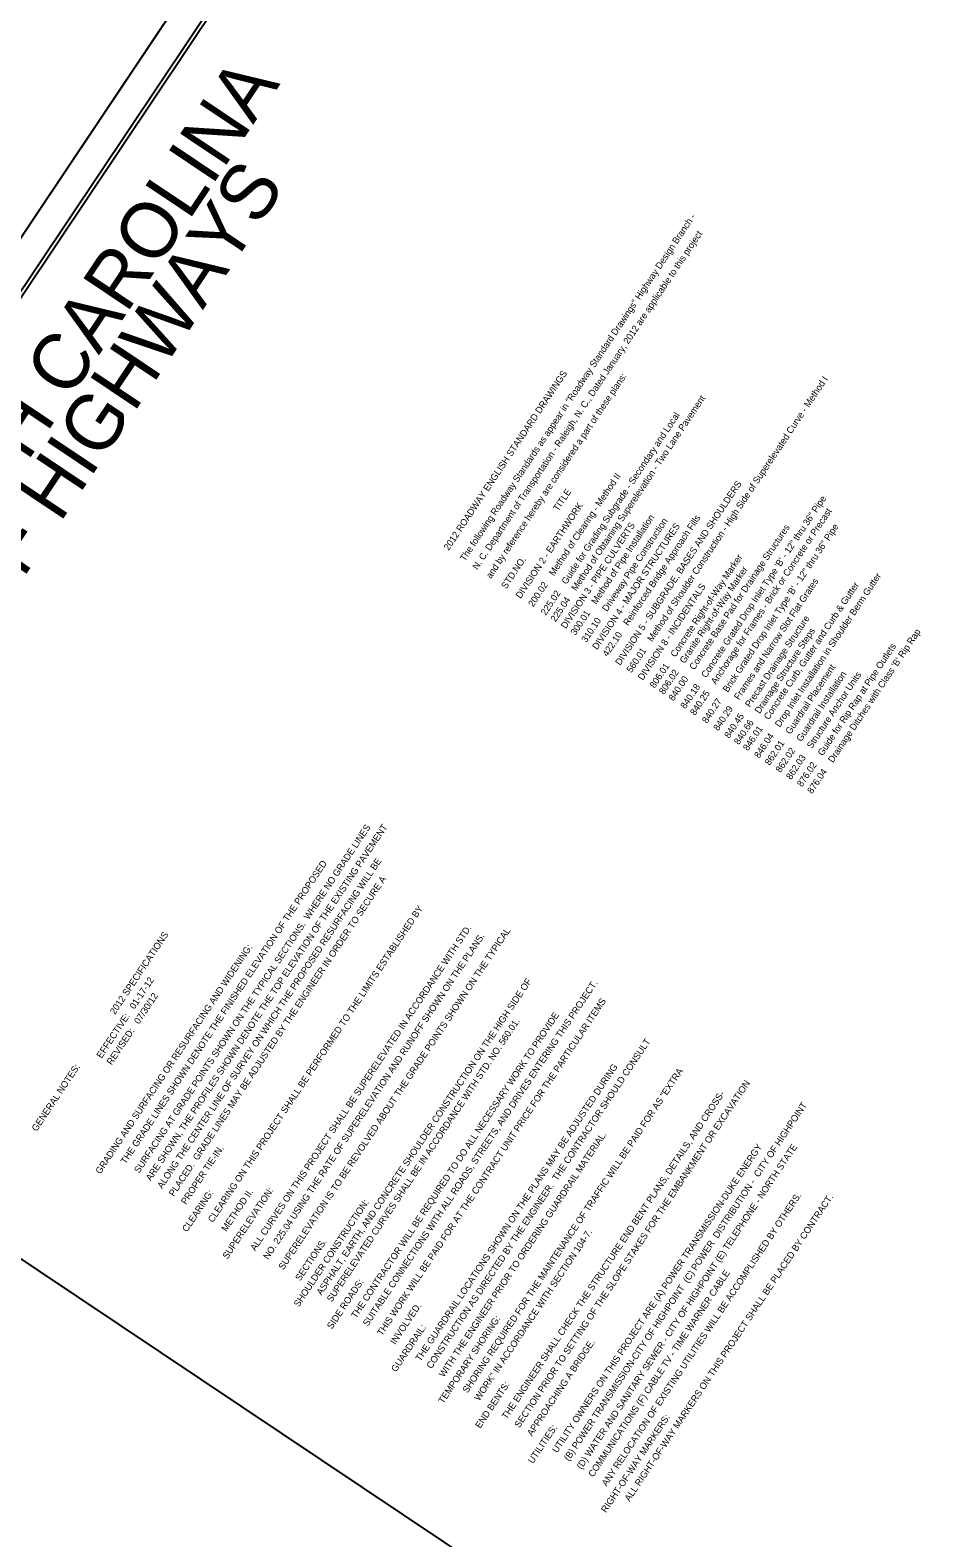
# Model space of a CAD drawing. Extents: x 1715610 to 1720914, y 798298 to 802505.
# Drawn here: x 1719710 to 1720322, y 798983 to 799997 of the extents above; entities that cross this region are included whole.
import ezdxf

# ---------------------------------------------------------------- set-up
doc = ezdxf.new("R2010")
doc.units = 0
for name, color, linetype in [('Default', 7, 'Continuous'), ('Sheet Cutting Line CELL', 7, 'Continuous'), ('Sheet Plan CELL', 7, 'Continuous'), ('Sheet Plot Border Inside CELL', 7, 'Continuous'), ('Sheet Plot Border Outside CELL', 7, 'Continuous'), ('Sheet Title CELL', 7, 'Continuous')]:
    doc.layers.add(name, color=color, linetype=linetype)

msp = doc.modelspace()

# ---------------------------------------------------------------- linework, layer by layer
at = {"layer": 'Default'}
msp.add_lwpolyline([(1719835.5, 798633.5), (1720043.1, 798943.6), (1719661.6, 799198.9), (1719454, 798888.8)], close=True, dxfattribs=at)
at = {"layer": 'Sheet Cutting Line CELL'}
msp.add_line((1720004.3, 800305.9), (1719067.9, 798906.9), dxfattribs=at)
at = {"layer": 'Sheet Plan CELL'}
msp.add_lwpolyline([(1720013.5, 800279.3), (1719179.2, 799032.7), (1720051.8, 798448.7), (1720886.1, 799695.2)], close=True, dxfattribs=at)
at = {"layer": 'Sheet Plot Border Inside CELL'}
msp.add_lwpolyline([(1719968.5, 798319.7), (1720895.2, 799704.2), (1720018.4, 800291.1), (1719091.7, 798906.6)], close=True, dxfattribs=at)
at = {"layer": 'Sheet Plot Border Outside CELL'}
msp.add_lwpolyline([(1719977.9, 798297.8), (1720914.3, 799696.9), (1720004.3, 800305.9), (1719067.9, 798906.9)], close=True, dxfattribs=at)

# ---------------------------------------------------------------- texts
at = {"layer": 'Default'}
for s, p in [('The following Roadway Standards as appear in "Roadway Standard Drawings" Highway Design Branch -', (1720003, 799639.3)), ('N. C. Department of Transportation - Raleigh, N. C., Dated January, 2012 are applicable to this project', (1720011.4, 799633.6)), ('2012 ROADWAY ENGLISH STANDARD DRAWINGS', (1719992.1, 799646.6)), ('and by reference hereby are considered a part of these plans:', (1720020.5, 799627.6)), ('560.01    Method of Shoulder Construction - High Side of Superelevated Curve - Method I', (1720115.1, 799564.3)), ('225.04    Method of Obtaining Superelevation - Two Lane Pavement', (1720064, 799598.5)), ('225.02    Guide for Grading Subgrade - Secondary and Local', (1720057.4, 799602.9)), ('200.02    Method of Clearing - Method II', (1720048.9, 799608.6)), ('STD.NO.                       TITLE', (1720030.8, 799620.7)), ('DIVISION 5 - SUBGRADE, BASES AND SHOULDERS', (1720107.5, 799569.3)), ('DIVISION 2 - EARTHWORK', (1720040.5, 799614.2)), ('840.18    Concrete Grated Drop Inlet Type \'B\' - 12" thru 36" Pipe', (1720151.4, 799540)), ('300.01    Method of Pipe Installation ', (1720077.4, 799589.5)), ('310.10    Driveway Pipe Construction', (1720084.7, 799584.6)), ('422.10    Reinforced Bridge Approach Fills', (1720098.9, 799575.1)), ('840.25    Anchorage for Frames - Brick or Concrete or Precast', (1720157.9, 799535.6)), ('DIVISION 3 - PIPE CULVERTS', (1720070.9, 799593.9)), ('DIVISION 4 - MAJOR STRUCTURES', (1720092, 799579.8)), ('840.00    Concrete Base Pad for Drainage Structures', (1720143.4, 799545.3)), ('840.27    Brick Grated Drop Inlet Type \'B\' - 12" thru 36" Pipe', (1720165.9, 799530.3)), ('806.01    Concrete Right-of-Way Marker', (1720130.7, 799553.9)), ('806.02    Granite Right-of-Way Marker', (1720136.9, 799549.7)), ('840.29    Frames and Narrow Slot Flat Grates', (1720173.5, 799525.2)), ('846.04    Drop Inlet Installation in Shoulder Berm Gutter', (1720201, 799506.8)), ('DIVISION 8 - INCIDENTALS', (1720122.7, 799559.2)), ('846.01    Concrete Curb, Gutter and Curb & Gutter', (1720193.5, 799511.8)), ('840.45    Precast Drainage Structure', (1720180.9, 799520.2)), ('840.66    Drainage Structure Steps', (1720187.4, 799515.9)), ("876.04    Drainage Ditches with Class 'B' Rip Rap", (1720236.7, 799482.9)), ('876.02    Guide for Rip Rap at Pipe Outlets', (1720229.8, 799487.5)), ('862.01    Guardrail Placement', (1720208.1, 799502)), ('862.02    Guardrail Installation', (1720215.4, 799497.1)), ('862.03    Structure Anchor Units', (1720222.5, 799492.4)), ('         SURFACING AT GRADE POINTS SHOWN ON THE TYPICAL SECTIONS.  WHERE NO GRADE LINES ', (1719775.4, 799215.1)), ('         ARE SHOWN, THE PROFILES SHOWN DENOTE THE TOP ELEVATION OF THE EXISTING PAVEMENT ', (1719783.2, 799209.9)), ('         THE GRADE LINES SHOWN DENOTE THE FINISHED ELEVATION OF THE PROPOSED ', (1719766.3, 799221.2)), ('         ALONG THE CENTER LINE OF SURVEY ON WHICH THE PROPOSED RESURFACING WILL BE ', (1719790.9, 799204.7)), ('         PLACED.  GRADE LINES MAY BE ADJUSTED BY THE ENGINEER IN ORDER TO SECURE A ', (1719798.7, 799199.5)), ('         CLEARING ON THIS PROJECT SHALL BE PERFORMED TO THE LIMITS ESTABLISHED BY ', (1719825, 799181.9)), ('         ALL CURVES ON THIS PROJECT SHALL BE SUPERELEVATED IN ACCORDANCE WITH STD. ', (1719853.5, 799162.8)), ('GENERAL NOTES:                         2012 SPECIFICATIONS', (1719714.8, 799255.7)), ('         NO. 225.04 USING THE RATE OF SUPERELEVATION AND RUNOFF SHOWN ON THE PLANS.', (1719862.2, 799157)), ('         SUPERELEVATION IS TO BE REVOLVED ABOUT THE GRADE POINTS SHOWN ON THE TYPICAL ', (1719872.5, 799150.1)), ('GRADING AND SURFACING OR RESURFACING AND WIDENING:  ', (1719757.7, 799227)), ('                                       EFFECTIVE:   01-17-12', (1719722.2, 799250.7)), ('         ASPHALT, EARTH, AND CONCRETE SHOULDER CONSTRUCTION ON THE HIGH SIDE OF', (1719898.1, 799133)), ('         SUITABLE CONNECTIONS WITH ALL ROADS, STREETS, AND DRIVES ENTERING THIS PROJECT.  ', (1719929.3, 799112.1)), ('                                       REVISED:   07/30/12', (1719729, 799246.2)), ('         THIS WORK WILL BE PAID FOR AT THE CONTRACT UNIT PRICE FOR THE PARTICULAR ITEMS ', (1719938.9, 799105.7)), ('         THE CONTRACTOR WILL BE REQUIRED TO DO ALL NECESSARY WORK TO PROVIDE ', (1719921.4, 799117.4)), ('         SUPERELEVATED CURVES SHALL BE IN ACCORDANCE WITH STD. NO. 560.01.', (1719905, 799128.4)), ('         CONSTRUCTION AS DIRECTED BY THE ENGINEER.  THE CONTRACTOR SHOULD CONSULT', (1719972.1, 799083.5)), ('         THE GUARDRAIL LOCATIONS SHOWN ON THE PLANS MAY BE ADJUSTED DURING ', (1719964.7, 799088.5)), ('         SHORING REQUIRED FOR THE MAINTENANCE OF TRAFFIC WILL BE PAID FOR AS "EXTRA ', (1719996.4, 799067.2)), ('         THE ENGINEER SHALL CHECK THE STRUCTURE END BENT PLANS, DETAILS, AND CROSS-', (1720022.8, 799049.5)), ('         SECTION PRIOR TO SETTING OF THE SLOPE STAKES FOR THE EMBANKMENT OR EXCAVATION ', (1720031.3, 799043.8)), ('         (B) POWER TRANSMISSION-CITY OF HIGHPOINT  (C) POWER  DISTRIBUTION -  CITY OF HIGHPOINT', (1720064.6, 799021.5)), ('         WITH THE ENGINEER PRIOR TO ORDERING GUARDRAIL MATERIAL.', (1719980.5, 799077.8)), ('         PROPER TIE-IN.  ', (1719806.9, 799194)), ('         UTILITY OWNERS ON THIS PROJECT ARE (A) POWER TRANSMISSION-DUKE ENERGY', (1720056.7, 799026.9)), ('         (D) WATER AND SANITARY SEWER - CITY OF HIGHPOINT (E) TELEPHONE - NORTH STATE', (1720073.1, 799015.9)), ('CLEARING:  ', (1719816, 799188)), ('         METHOD II.', (1719834.1, 799175.8)), ('SUPERELEVATION:  ', (1719843.2, 799169.8)), ('         ANY RELOCATION OF EXISTING UTILITIES WILL BE ACCOMPLISHED BY OTHERS.  ', (1720090, 799004.5)), ('         ALL RIGHT-OF-WAY MARKERS ON THIS PROJECT SHALL BE PLACED BY CONTRACT.  ', (1720105.4, 798994.3)), ('SHOULDER CONSTRUCTION:  ', (1719891.2, 799137.6)), ('         SECTIONS.  ', (1719883.8, 799142.6)), ('         WORK" IN ACCORDANCE WITH SECTION 104-7.  ', (1720004.3, 799061.9)), ('         COMMUNICATIONS (F) CABLE TV - TIME WARNER CABLE', (1720081, 799010.6)), ('SIDE ROADS:  ', (1719913.5, 799122.7)), ('         INVOLVED.  ', (1719947.7, 799099.8)), ('TEMPORARY SHORING:  ', (1719988.5, 799072.5)), ('GUARDRAIL:  ', (1719956.7, 799093.8)), ('         APPROACHING A BRIDGE.  ', (1720039.8, 799038.2)), ('END BENTS:  ', (1720013.3, 799055.9)), ('UTILITIES:  ', (1720048.8, 799032.2)), ('RIGHT-OF-WAY MARKERS:  ', (1720098, 798999.2))]:
    msp.add_text(s, height=4.5, rotation=56.2051, dxfattribs=at).set_placement(p)
at = {"layer": 'Sheet Title CELL'}
for s, p in [('STATE OF NORTH CAROLINA', (1719485.4, 799372.9)), ('DIVISION OF HIGHWAYS', (1719553.8, 799401))]:
    msp.add_text(s, height=37.5, rotation=56.2051, dxfattribs=at).set_placement(p)

doc.saveas('drawing.dxf')
